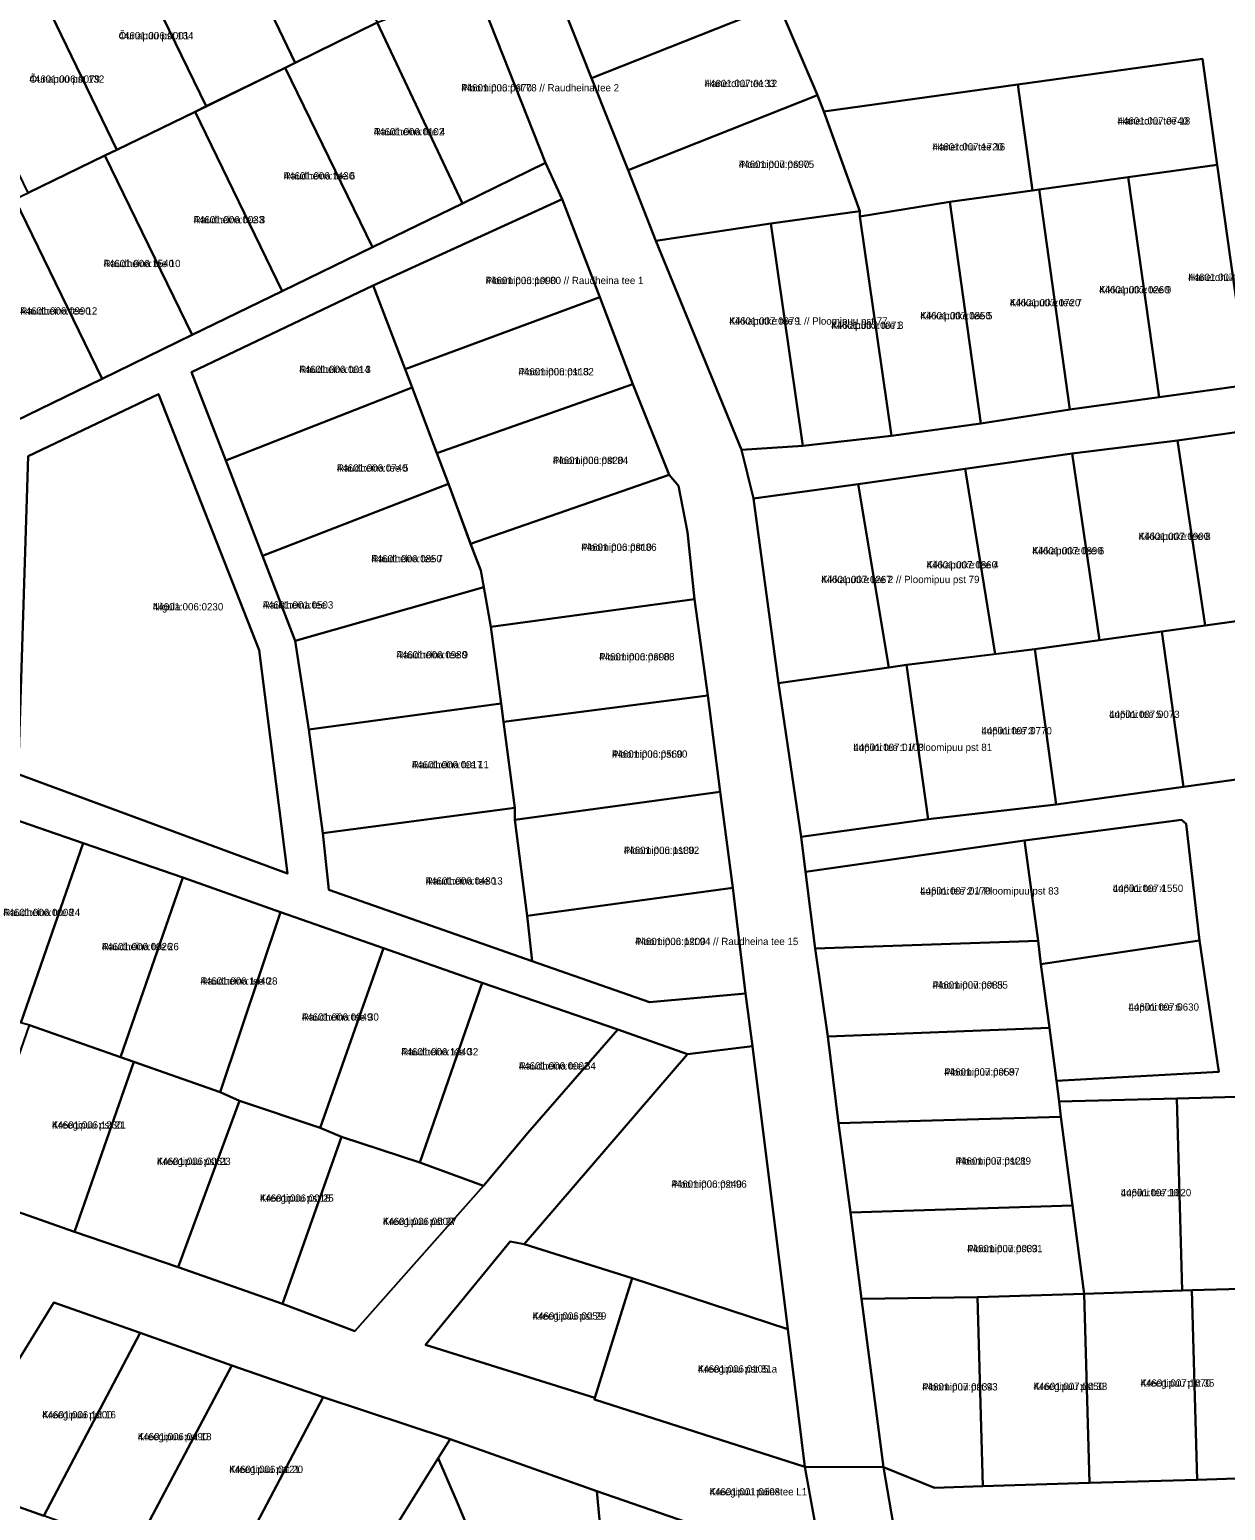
# Model space of a CAD drawing. Extents: x 551843 to 558501, y 6589003 to 6595718.
# Drawn here: x 553872.3 to 554118.2, y 6593051.3 to 6593355.7 of the extents above; entities that cross this region are included whole.
import ezdxf

# ---------------------------------------------------------------- set-up
doc = ezdxf.new("R2010")
doc.units = 0
for name, color, linetype in [('L_AADRESS', 7, 'Continuous'), ('PIIR', 7, 'Continuous'), ('TUNNUS', 7, 'Continuous')]:
    doc.layers.add(name, color=color, linetype=linetype)

msp = doc.modelspace()

# ---------------------------------------------------------------- linework, layer by layer
at = {"layer": 'PIIR'}
for points in [[(553927.51, 6593393.79), (553943.74, 6593357.21), (553926.91, 6593348.89), (553909.52, 6593385.26)], [(553909.52, 6593385.26), (553926.91, 6593348.89), (553924.84, 6593347.89), (553908.6, 6593339.99), (553890.9, 6593376.42)], [(553980.29, 6593364.84), (554018.84, 6593379.9), (554026.14, 6593361.42), (554026.31, 6593360.98), (553987.82, 6593345.77)], [(553872.59, 6593367.51), (553890.9, 6593376.42), (553908.6, 6593339.99), (553906.31, 6593338.87), (553890.23, 6593331.05)], [(553854.3, 6593358.62), (553872.59, 6593367.51), (553890.23, 6593331.05), (553887.78, 6593329.87), (553871.99, 6593322.18)], [(553945.21, 6593357.79), (553961.85, 6593365.98), (553963.28, 6593366.56), (553978.42, 6593328.33), (553961.3, 6593320.01), (553943.74, 6593357.21)], [(553987.82, 6593345.77), (554026.31, 6593360.98), (554034.35, 6593342.28), (553995.37, 6593326.88)], [(553961.3, 6593320.01), (553942.78, 6593311.01), (553924.84, 6593347.89), (553926.91, 6593348.89), (553943.74, 6593357.21)], [(554075.54, 6593344.48), (554113.5, 6593349.76), (554116.53, 6593327.97), (554098.21, 6593325.42), (554079.89, 6593322.87), (554078.57, 6593322.69)], [(553924.84, 6593347.89), (553942.78, 6593311.01), (553924.25, 6593301.99), (553906.31, 6593338.87)], [(554043.04, 6593318.43), (554043.04, 6593318.44), (554035.63, 6593338.89), (554075.54, 6593344.48), (554078.57, 6593322.69), (554061.56, 6593320.33), (554043.04, 6593317.33)], [(554034.35, 6593342.28), (554035.63, 6593338.89), (554043.04, 6593318.43), (554024.76, 6593315.9), (554001.08, 6593312.34), (553995.37, 6593326.88)], [(553890.23, 6593331.05), (553906.31, 6593338.87), (553924.25, 6593301.99), (553905.73, 6593292.98), (553887.78, 6593329.87)], [(553887.78, 6593329.87), (553905.73, 6593292.98), (553887.19, 6593283.97), (553869.25, 6593320.86), (553871.99, 6593322.18)], [(554079.89, 6593322.87), (554098.21, 6593325.42), (554104.61, 6593280.19), (554086.19, 6593277.62)], [(554116.53, 6593327.97), (554122.93, 6593282.74), (554104.61, 6593280.19), (554098.21, 6593325.42)], [(554078.57, 6593322.69), (554079.89, 6593322.87), (554086.19, 6593277.62), (554067.9, 6593274.76), (554061.56, 6593320.33)], [(553869.25, 6593320.86), (553887.19, 6593283.97), (553864.2, 6593272.79), (553859.74, 6593289.98), (553853.55, 6593313.74)], [(553949.51, 6593285.97), (553942.92, 6593303.12), (553981.84, 6593320.9), (553989.59, 6593300.71)], [(554043.04, 6593317.33), (554061.56, 6593320.33), (554067.9, 6593274.76), (554049.57, 6593272.22)], [(554024.76, 6593315.9), (554043.04, 6593318.43), (554043.04, 6593317.33), (554049.57, 6593272.22), (554031.29, 6593270.18)], [(554024.76, 6593315.9), (554031.29, 6593270.18), (554018.73, 6593269.37), (554001.08, 6593312.34)], [(553905.62, 6593285.31), (553942.92, 6593303.12), (553949.51, 6593285.97), (553950.95, 6593282.19), (553912.63, 6593267.17)], [(553949.51, 6593285.97), (553989.59, 6593300.71), (553996.36, 6593282.84), (553956.05, 6593268.65), (553950.95, 6593282.19)], [(553996.36, 6593282.84), (554003.81, 6593264.2), (553963, 6593250.06), (553958.44, 6593262.36), (553956.05, 6593268.65)], [(553898.78, 6593280.77), (553919.51, 6593228.18), (553925.34, 6593182.28), (553869.91, 6593202.68), (553872.03, 6593268.08)], [(553872.03, 6593268.08), (553869.91, 6593202.68), (553925.34, 6593182.28), (553919.51, 6593228.18), (553898.78, 6593280.77)], [(553912.63, 6593267.17), (553950.95, 6593282.19), (553956.05, 6593268.65), (553958.44, 6593262.36), (553920.19, 6593247.58)], [(554131.2, 6593274.53), (554134.82, 6593236.12), (554131.32, 6593235.64), (554114.03, 6593233.23), (554108.36, 6593271.31)], [(554086.68, 6593268.58), (554108.36, 6593271.31), (554114.03, 6593233.23), (554105.17, 6593232), (554092.29, 6593230.21)], [(554086.68, 6593268.58), (554092.29, 6593230.21), (554079.01, 6593228.37), (554070.84, 6593227.37), (554064.68, 6593265.44)], [(554048.98, 6593224.61), (554042.66, 6593262.3), (554064.68, 6593265.44), (554070.84, 6593227.37), (554052.63, 6593225.14)], [(553958.44, 6593262.36), (553963.59, 6593248.46), (553965.07, 6593244.55), (553965.68, 6593241.1), (553926.89, 6593230.12), (553920.19, 6593247.58)], [(554003.81, 6593264.2), (554005.75, 6593261.93), (554007.57, 6593252.43), (554009.01, 6593238.68), (553967.14, 6593233), (553965.68, 6593241.1), (553965.07, 6593244.55), (553963.59, 6593248.46), (553963, 6593250.06)], [(554021.19, 6593259.36), (554042.66, 6593262.3), (554048.98, 6593224.61), (554026.33, 6593221.42)], [(553926.89, 6593230.12), (553965.68, 6593241.1), (553967.14, 6593233), (553969.28, 6593217.23), (553929.74, 6593211.85)], [(553969.28, 6593217.23), (553967.14, 6593233), (554009.01, 6593238.68), (554011.76, 6593218.86), (553969.77, 6593213.46)], [(554105.17, 6593232), (554114.03, 6593233.23), (554131.32, 6593235.64), (554135.74, 6593203.74), (554109.59, 6593200.1)], [(554079.01, 6593228.37), (554092.29, 6593230.21), (554105.17, 6593232), (554109.59, 6593200.1), (554083.43, 6593196.48)], [(554079.01, 6593228.37), (554083.43, 6593196.48), (554057.06, 6593193.45), (554052.63, 6593225.14)], [(554048.98, 6593224.61), (554052.63, 6593225.14), (554057.06, 6593193.45), (554030.96, 6593189.82), (554026.33, 6593221.42)], [(553972.08, 6593195.75), (553969.77, 6593213.46), (554011.76, 6593218.86), (554014.3, 6593199.04), (553972.11, 6593193.28)], [(553969.28, 6593217.23), (553969.77, 6593213.46), (553972.08, 6593195.75), (553932.59, 6593190.57), (553929.74, 6593211.85)], [(553972.11, 6593193.28), (554014.3, 6593199.04), (554016.92, 6593179.32), (553974.65, 6593173.55)], [(553851.18, 6593160.89), (553857.12, 6593179.46), (553861.39, 6593192.79), (553861.46, 6593196.05), (553883.28, 6593188.51), (553870.51, 6593151.58), (553850.43, 6593158.51)], [(553932.59, 6593190.57), (553972.08, 6593195.75), (553972.11, 6593193.28), (553974.65, 6593173.55), (553975.62, 6593164.23), (553933.8, 6593178.92)], [(554110.16, 6593192.47), (554112.89, 6593168.46), (554080.23, 6593163.65), (554079.69, 6593168.42), (554076.9, 6593189.02), (554109.17, 6593193.3)], [(553903.79, 6593181.43), (553890.99, 6593144.48), (553872.28, 6593151.07), (553870.51, 6593151.58), (553883.28, 6593188.51)], [(554076.9, 6593189.02), (554079.69, 6593168.42), (554033.87, 6593166.86), (554031.88, 6593182.62)], [(553923.86, 6593174.3), (553911.49, 6593137.28), (553893.7, 6593143.53), (553890.99, 6593144.48), (553903.79, 6593181.43)], [(553999.75, 6593155.79), (553975.62, 6593164.23), (553974.65, 6593173.55), (554016.92, 6593179.32), (554019.55, 6593157.62)], [(553945.07, 6593166.9), (553932.08, 6593130), (553915.46, 6593135.55), (553911.49, 6593137.28), (553923.86, 6593174.3)], [(553965.36, 6593159.8), (553952.58, 6593122.85), (553936.47, 6593128.14), (553932.08, 6593130), (553945.07, 6593166.9)], [(554033.87, 6593166.86), (554079.69, 6593168.42), (554080.23, 6593163.65), (554082.05, 6593150.51), (554036.43, 6593148.77)], [(554082.05, 6593150.51), (554080.23, 6593163.65), (554112.89, 6593168.46), (554116.84, 6593141.5), (554083.51, 6593139.67)], [(553993.24, 6593150.17), (553974.77, 6593128.95), (553965.62, 6593118.07), (553952.58, 6593122.85), (553965.36, 6593159.8)], [(553890.99, 6593144.48), (553893.7, 6593143.53), (553881.51, 6593108.6), (553860.1, 6593116.14), (553872.28, 6593151.07)], [(554082.05, 6593150.51), (554083.51, 6593139.67), (554084.04, 6593135.36), (554084.36, 6593132.26), (554038.67, 6593130.95), (554036.43, 6593148.77)], [(554020.99, 6593146.78), (554028.21, 6593088.56), (553996.19, 6593099.06), (553973.99, 6593106.07), (554007.57, 6593145.12)], [(553893.7, 6593143.53), (553911.49, 6593137.28), (553915.46, 6593135.55), (553902.87, 6593101.36), (553881.51, 6593108.6)], [(554130.47, 6593136.64), (554131.56, 6593097.15), (554111.31, 6593096.59), (554109.34, 6593096.54), (554108.25, 6593136.03)], [(553932.08, 6593130), (553936.47, 6593128.14), (553924.28, 6593093.82), (553902.87, 6593101.36), (553915.46, 6593135.55)], [(554086.78, 6593114.01), (554084.36, 6593132.26), (554084.04, 6593135.36), (554108.25, 6593136.03), (554109.34, 6593096.54), (554089.16, 6593095.88)], [(554041.15, 6593112.57), (554038.67, 6593130.95), (554084.36, 6593132.26), (554086.78, 6593114.01)], [(553936.47, 6593128.14), (553952.58, 6593122.85), (553965.62, 6593118.07), (553939.21, 6593088.15), (553924.28, 6593093.82)], [(554089.16, 6593095.88), (554067.23, 6593095.18), (554043.39, 6593094.82), (554041.15, 6593112.57), (554086.78, 6593114.01)], [(553953.7, 6593085.37), (553971.14, 6593106.63), (553973.99, 6593106.07), (553996.19, 6593099.06), (553988.53, 6593074.47)], [(553988.53, 6593074.47), (553996.22, 6593099.06), (554028.21, 6593088.56), (554031.74, 6593060.29), (553988.44, 6593074.16)], [(554112.39, 6593057.6), (554111.31, 6593096.59), (554131.56, 6593097.15), (554133.43, 6593097.09), (554134.48, 6593058.36)], [(553854.75, 6593057.46), (553877.3, 6593094.1), (553895.01, 6593087.85), (553875.19, 6593050.25)], [(554068.35, 6593056.31), (554058.37, 6593055.94), (554047.89, 6593060.25), (554043.39, 6593094.82), (554067.23, 6593095.18)], [(554067.23, 6593095.18), (554089.16, 6593095.88), (554090.27, 6593056.99), (554068.35, 6593056.31)], [(554089.16, 6593095.88), (554109.34, 6593096.54), (554111.31, 6593096.59), (554112.39, 6593057.6), (554090.27, 6593056.99)], [(553913.88, 6593081.12), (553894.03, 6593043.62), (553878.12, 6593049.22), (553875.19, 6593050.25), (553895.01, 6593087.85)], [(553913.88, 6593081.12), (553932.68, 6593074.58), (553912.87, 6593037.01), (553894.03, 6593043.62)], [(553988.97, 6593055.28), (553992.55, 6593016.61), (553976.81, 6593014.6), (553976, 6593015.3), (553960.37, 6593052.69), (553956.34, 6593062.1), (553958.82, 6593066)], [(553956.34, 6593062.1), (553960.37, 6593052.69), (553976, 6593015.3), (553969.07, 6593008.89), (553936.54, 6593030.26)], [(554031.39, 6593040.61), (554000.05, 6593014.53), (553992.55, 6593016.61), (553988.97, 6593055.28)]]:
    msp.add_lwpolyline(points, close=True, dxfattribs=at)
for points in [[(553980.29, 6593364.84), (553987.82, 6593345.77), (553995.37, 6593326.88), (554001.08, 6593312.34), (554018.73, 6593269.37), (554021.19, 6593259.36), (554026.33, 6593221.42), (554030.96, 6593189.82), (554031.88, 6593182.62), (554033.87, 6593166.86), (554036.43, 6593148.77), (554038.67, 6593130.95), (554041.15, 6593112.57), (554043.39, 6593094.82), (554047.89, 6593060.25), (554031.74, 6593060.29), (554028.21, 6593088.56), (554020.99, 6593146.78), (554019.55, 6593157.62), (554016.92, 6593179.32), (554014.3, 6593199.04), (554011.76, 6593218.86), (554009.01, 6593238.68), (554007.57, 6593252.43), (554005.75, 6593261.93), (554003.81, 6593264.2), (553996.36, 6593282.84), (553989.59, 6593300.71), (553981.84, 6593320.9), (553978.42, 6593328.33), (553963.28, 6593366.56)], [(554131.2, 6593274.53), (554108.36, 6593271.31), (554086.68, 6593268.58), (554064.68, 6593265.44), (554042.66, 6593262.3), (554021.19, 6593259.36), (554018.73, 6593269.37), (554031.29, 6593270.18), (554049.57, 6593272.22), (554067.9, 6593274.76), (554086.19, 6593277.62), (554104.61, 6593280.19), (554122.93, 6593282.74), (554116.53, 6593327.97), (554113.5, 6593349.76), (554075.54, 6593344.48), (554035.63, 6593338.89), (554034.35, 6593342.28), (554026.31, 6593360.98)], [(553864.2, 6593272.79), (553887.19, 6593283.97), (553905.73, 6593292.98), (553924.25, 6593301.99), (553942.78, 6593311.01), (553961.3, 6593320.01), (553978.42, 6593328.33), (553981.84, 6593320.9), (553942.92, 6593303.12), (553905.62, 6593285.31), (553912.63, 6593267.17), (553920.19, 6593247.58), (553926.89, 6593230.12), (553929.74, 6593211.85), (553932.59, 6593190.57), (553933.8, 6593178.92), (553975.62, 6593164.23), (553999.75, 6593155.79), (554019.55, 6593157.62), (554020.99, 6593146.78), (554007.57, 6593145.12), (553993.24, 6593150.17), (553965.36, 6593159.8), (553945.07, 6593166.9), (553923.86, 6593174.3), (553903.79, 6593181.43), (553883.28, 6593188.51), (553861.46, 6593196.05)], [(554130.47, 6593136.64), (554108.25, 6593136.03), (554084.04, 6593135.36), (554083.51, 6593139.67), (554116.84, 6593141.5), (554112.89, 6593168.46), (554110.16, 6593192.47), (554109.17, 6593193.3), (554076.9, 6593189.02), (554031.88, 6593182.62), (554030.96, 6593189.82), (554057.06, 6593193.45), (554083.43, 6593196.48), (554109.59, 6593200.1), (554135.74, 6593203.74)], [(553702.95, 6593171.53), (553721.14, 6593165.08), (553739.77, 6593158.52), (553747.64, 6593155.65), (553789.06, 6593141.51), (553797.56, 6593137.62), (553839.15, 6593123.26), (553860.1, 6593116.14), (553881.51, 6593108.6), (553902.87, 6593101.36), (553924.28, 6593093.82), (553939.21, 6593088.15), (553965.62, 6593118.07), (553974.77, 6593128.95), (553993.24, 6593150.17), (554007.57, 6593145.12), (553973.99, 6593106.07), (553971.14, 6593106.63), (553953.7, 6593085.37), (553988.53, 6593074.47), (553988.44, 6593074.16), (554031.74, 6593060.29), (554035.59, 6593039.14)], [(554031.39, 6593040.61), (553988.97, 6593055.28), (553958.82, 6593066), (553932.68, 6593074.58), (553913.88, 6593081.12), (553895.01, 6593087.85), (553877.3, 6593094.1), (553854.75, 6593057.46), (553875.19, 6593050.25)], [(553912.87, 6593037.01), (553932.68, 6593074.58), (553958.82, 6593066), (553956.34, 6593062.1), (553936.54, 6593030.26)], [(554035.59, 6593039.14), (554031.74, 6593060.29), (554047.89, 6593060.25), (554051.46, 6593039.45)], [(554051.46, 6593039.45), (554047.89, 6593060.25), (554058.37, 6593055.94), (554068.35, 6593056.31), (554090.27, 6593056.99), (554112.39, 6593057.6), (554134.48, 6593058.36)]]:
    msp.add_lwpolyline(points, dxfattribs=at)

# ---------------------------------------------------------------- texts
at = {"layer": 'L_AADRESS'}
for s, p in [('Õunapuu pst 134', (553890.6, 6593353.75)), ('Õunapuu pst 132', (553872.26, 6593344.83)), ('Ploomipuu pst 78 // Raudheina tee 2', (553961.08, 6593343.04)), ('Hanerohu tee 12', (554011.1, 6593343.93)), ('Hanerohu tee 18', (554096.04, 6593336.23)), ('Raudheina tee 4', (553943.07, 6593334.01)), ('Hanerohu tee 16', (554057.98, 6593330.9)), ('Ploomipuu pst 75', (554018.14, 6593327.31)), ('Raudheina tee 6', (553924.55, 6593324.94)), ('Raudheina tee 8', (553906.02, 6593315.92)), ('Raudheina tee 10', (553887.49, 6593306.92)), ('Ploomipuu pst 80 // Raudheina tee 1', (553966.08, 6593303.43)), ('Hanerohu tee 20 // Kikkaputke tee 11', (554110.57, 6593304.08)), ('Kikkaputke tee 9', (554092.25, 6593301.53)), ('Raudheina tee 12', (553870.37, 6593297.17)), ('Kikkaputke tee 5', (554055.47, 6593296.19)), ('Kikkaputke tee 7', (554073.88, 6593298.87)), ('Kikkaputke tee 1 // Ploomipuu pst 77', (554016.18, 6593295.09)), ('Kikkaputke tee 3', (554037.16, 6593294.23)), ('Raudheina tee 3', (553927.75, 6593285.15)), ('Ploomipuu pst 82', (553972.83, 6593284.68)), ('Ploomipuu pst 84', (553979.9, 6593266.45)), ('Raudheina tee 5', (553935.5, 6593264.88)), ('Kikkaputke tee 8', (554100.36, 6593250.82)), ('Ploomipuu pst 86', (553985.75, 6593248.6)), ('Kikkaputke tee 6', (554078.48, 6593247.86)), ('Raudheina tee 7', (553942.57, 6593246.24)), ('Kikkaputke tee 4', (554056.75, 6593244.98)), ('Kikkaputke tee 2 // Ploomipuu pst 79', (554035.08, 6593241.96)), ('Nigula', (553897.62, 6593236.35)), ('Raudheina tee', (553920.25, 6593236.73)), ('Raudheina tee 9', (553947.74, 6593226.48)), ('Ploomipuu pst 88', (553989.42, 6593226.07)), ('Lupiini tee 5', (554094.3, 6593214.24)), ('Lupiini tee 3', (554068.03, 6593210.87)), ('Ploomipuu pst 90', (553992.07, 6593206.07)), ('Lupiini tee 1 // Ploomipuu pst 81', (554041.7, 6593207.45)), ('Raudheina tee 11', (553950.91, 6593203.9)), ('Ploomipuu pst 92', (553994.5, 6593186.29)), ('Raudheina tee 13', (553953.75, 6593179.99)), ('Lupiini tee 2 // Ploomipuu pst 83', (554055.44, 6593177.94)), ('Lupiini tee 4', (554095.04, 6593178.48)), ('Raudheina tee 24', (553866.86, 6593173.51)), ('Raudheina tee 26', (553887.15, 6593166.5)), ('Ploomipuu pst 94 // Raudheina tee 15', (553996.81, 6593167.55)), ('Raudheina tee 28', (553907.43, 6593159.42)), ('Ploomipuu pst 85', (554057.98, 6593158.6)), ('Lupiini tee 6', (554098.28, 6593154.07)), ('Raudheina tee 30', (553928.28, 6593152.01)), ('Raudheina tee 32', (553948.72, 6593144.87)), ('Raudheina tee 34', (553972.91, 6593141.97)), ('Ploomipuu pst 87', (554060.4, 6593140.73)), ('Kreegipuu pst 21', (553876.9, 6593129.83)), ('Kreegipuu pst 23', (553898.48, 6593122.35)), ('Ploomipuu pst 89', (554062.74, 6593122.42)), ('Ploomipuu pst 96', (554004.28, 6593117.67)), ('Kreegipuu pst 25', (553919.67, 6593114.79)), ('Lupiini tee 10', (554096.69, 6593115.92)), ('Kreegipuu pst 27', (553944.95, 6593110)), ('Ploomipuu pst 91', (554065.11, 6593104.42)), ('Kreegipuu pst 29', (553975.74, 6593090.55)), ('Kreegipuu pst 31a', (554009.74, 6593079.67)), ('Ploomipuu pst 93', (554055.87, 6593075.99)), ('Kreegipuu pst 33', (554078.75, 6593076.09)), ('Kreegipuu pst 35', (554100.77, 6593076.77)), ('Kreegipuu pst 16', (553874.88, 6593070.26)), ('Kreegipuu pst 18', (553894.54, 6593065.76)), ('Kreegipuu pst 20', (553913.36, 6593059.03)), ('Kreegipuu puiestee L1', (554012.13, 6593054.42))]:
    msp.add_text(s, height=1.5, dxfattribs=at).set_placement(p)
at = {"layer": 'TUNNUS'}
for s, p in [('44601:006:0001', (553890.6, 6593353.75)), ('44601:006:0079', (553872.26, 6593344.83)), ('44601:006:0670', (553961.08, 6593343.04)), ('44601:007:0133', (554011.1, 6593343.93)), ('44601:007:0740', (554096.04, 6593336.23)), ('44601:006:0102', (553943.07, 6593334.01)), ('44601:007:1720', (554057.98, 6593330.9)), ('44601:007:0690', (554018.14, 6593327.31)), ('44601:006:1430', (553924.55, 6593324.94)), ('44601:006:0033', (553906.02, 6593315.92)), ('44601:006:1540', (553887.49, 6593306.92)), ('44601:006:1090', (553966.08, 6593303.43)), ('44601:007:0065', (554110.57, 6593304.08)), ('44601:007:0260', (554092.25, 6593301.53)), ('44601:006:0990', (553870.37, 6593297.17)), ('44601:007:0720', (554073.88, 6593298.87)), ('44601:007:0079', (554016.18, 6593295.09)), ('44601:007:0071', (554037.16, 6593294.23)), ('44601:007:0850', (554055.47, 6593296.19)), ('44601:006:0014', (553927.75, 6593285.15)), ('44601:006:0113', (553972.83, 6593284.68)), ('44601:006:0820', (553979.9, 6593266.45)), ('44601:006:0740', (553935.5, 6593264.88)), ('44601:007:0900', (554100.36, 6593250.82)), ('44601:006:0810', (553985.75, 6593248.6)), ('44601:007:0890', (554078.48, 6593247.86)), ('44601:006:0850', (553942.57, 6593246.24)), ('44601:007:0860', (554056.75, 6593244.98)), ('44601:007:0267', (554035.08, 6593241.96)), ('44601:006:0230', (553897.62, 6593236.35)), ('44601:001:0503', (553920.25, 6593236.73)), ('44601:006:0980', (553947.74, 6593226.48)), ('44601:006:0690', (553989.42, 6593226.07)), ('44601:007:0073', (554094.3, 6593214.24)), ('44601:007:0770', (554068.03, 6593210.87)), ('44601:006:0560', (553992.07, 6593206.07)), ('44601:007:0100', (554041.7, 6593207.45)), ('44601:006:0017', (553950.91, 6593203.9)), ('44601:006:1130', (553994.5, 6593186.29)), ('44601:006:0480', (553953.75, 6593179.99)), ('44601:007:0170', (554055.44, 6593177.94)), ('44601:007:1550', (554095.04, 6593178.48)), ('44601:006:0008', (553866.86, 6593173.51)), ('44601:006:0026', (553887.15, 6593166.5)), ('44601:006:1200', (553996.81, 6593167.55)), ('44601:006:1440', (553907.43, 6593159.42)), ('44601:007:0085', (554057.98, 6593158.6)), ('44601:007:0630', (554098.28, 6593154.07)), ('44601:006:0049', (553928.28, 6593152.01)), ('44601:006:1340', (553948.72, 6593144.87)), ('44601:006:0002', (553972.91, 6593141.97)), ('44601:007:0059', (554060.4, 6593140.73)), ('44601:006:1230', (553876.9, 6593129.83)), ('44601:006:0061', (553898.48, 6593122.35)), ('44601:007:0121', (554062.74, 6593122.42)), ('44601:006:0240', (554004.28, 6593117.67)), ('44601:006:0018', (553919.67, 6593114.79)), ('44601:007:1620', (554096.69, 6593115.92)), ('44601:006:0500', (553944.95, 6593110)), ('44601:007:0033', (554065.11, 6593104.42)), ('44601:006:0059', (553975.74, 6593090.55)), ('44601:006:0105', (554009.74, 6593079.67)), ('44601:007:0034', (554055.87, 6593075.99)), ('44601:007:0650', (554078.75, 6593076.09)), ('44601:007:1670', (554100.77, 6593076.77)), ('44601:006:1500', (553874.88, 6593070.26)), ('44601:006:0490', (553894.54, 6593065.76)), ('44601:006:0121', (553913.36, 6593059.03)), ('44601:001:0608', (554012.13, 6593054.42))]:
    msp.add_text(s, height=1.5, dxfattribs=at).set_placement(p)

doc.saveas('drawing.dxf')
